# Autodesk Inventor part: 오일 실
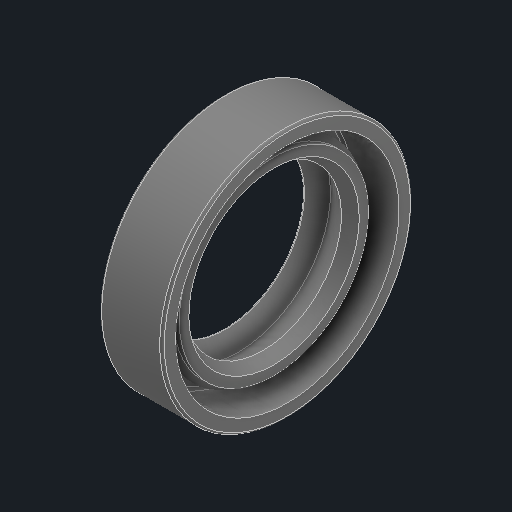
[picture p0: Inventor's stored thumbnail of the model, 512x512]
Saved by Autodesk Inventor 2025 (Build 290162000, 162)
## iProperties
Created: 2025-08
Part Number: 오일 실
Material: 고무
Description: 오일-실
Document SubType Name: Modeling
Designer: infra005
Density: 0.93 g/cm^3
Appearance: 기본값
Author: jhkim
Sending System: Autodesk Inventor 2026
Preprocessor: ST-DEVELOPER v20.1
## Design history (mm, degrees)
feature "Solid1"
node "솔리드1"
